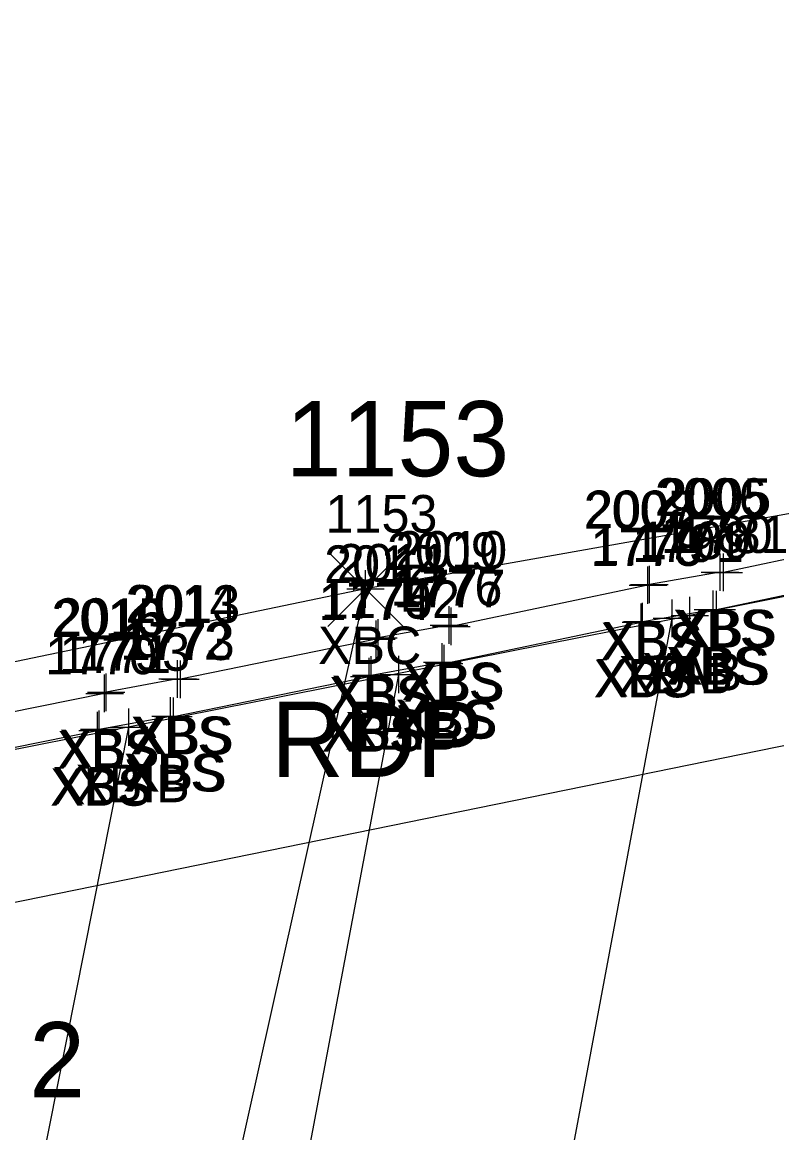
# Model space of a CAD drawing. Extents: x 1683147 to 1683637, y 416837 to 418211.
# Drawn here: x 1683260.07 to 1683280.15, y 417636.48 to 417666.03 of the extents above; entities that cross this region are included whole.
import ezdxf

# ---------------------------------------------------------------- set-up
doc = ezdxf.new("R2010")
doc.units = 0
for name, color, linetype in [('B_A', 7, 'Continuous'), ('B_I', 7, 'Continuous'), ('B_TIC', 7, 'Continuous'), ('BB', 7, 'Continuous'), ('BELB', 7, 'Continuous'), ('BSE', 7, 'Continuous'), ('BSUBM', 7, 'Continuous'), ('C_C', 7, 'Continuous'), ('LELB', 7, 'Continuous'), ('P_A', 7, 'Continuous'), ('P_I', 7, 'Continuous'), ('P_TIC', 7, 'Continuous'), ('PET', 7, 'Continuous')]:
    doc.layers.add(name, color=color, linetype=linetype)

msp = doc.modelspace()

# ---------------------------------------------------------------- linework, layer by layer
at = {"layer": 'B_TIC'}
for p, q in [((1683278.641, 417651.395), (1683278.717, 417651.395)), ((1683278.736, 417651.389), (1683278.812, 417651.389)), ((1683276.722, 417651.05), (1683276.798, 417651.05)), ((1683276.761, 417651.068), (1683276.837, 417651.068)), ((1683269.209, 417650.948), (1683269.285, 417650.948)), ((1683278.455, 417650.406), (1683278.53, 417650.406)), ((1683278.551, 417650.401), (1683278.627, 417650.401)), ((1683277.366, 417650.167), (1683277.441, 417650.167)), ((1683277.838, 417650.241), (1683277.914, 417650.241)), ((1683277.838, 417650.241), (1683277.914, 417650.241)), ((1683271.431, 417649.988), (1683271.507, 417649.988)), ((1683271.491, 417649.952), (1683271.567, 417649.952)), ((1683276.54, 417650.063), (1683276.616, 417650.063)), ((1683276.576, 417650.08), (1683276.651, 417650.08)), ((1683269.493, 417649.608), (1683269.569, 417649.608)), ((1683269.547, 417649.645), (1683269.623, 417649.645)), ((1683271.251, 417649.003), (1683271.326, 417649.003)), ((1683271.302, 417648.963), (1683271.377, 417648.963)), ((1683269.363, 417648.657), (1683269.438, 417648.657)), ((1683270.093, 417648.672), (1683270.169, 417648.672)), ((1683264.21, 417648.553), (1683264.286, 417648.553)), ((1683264.284, 417648.546), (1683264.36, 417648.546)), ((1683269.305, 417648.618), (1683269.381, 417648.618)), ((1683262.266, 417648.169), (1683262.342, 417648.169)), ((1683262.308, 417648.2), (1683262.384, 417648.2)), ((1683264.024, 417647.565), (1683264.1, 417647.565)), ((1683264.098, 417647.557), (1683264.174, 417647.557)), ((1683262.077, 417647.179), (1683262.153, 417647.179)), ((1683262.125, 417647.213), (1683262.2, 417647.213)), ((1683262.913, 417647.271), (1683262.989, 417647.271))]:
    msp.add_line(p, q, dxfattribs=at)
for points in [[(1683278.638, 417650.895), (1683278.638, 417651.895)], [(1683278.733, 417650.889), (1683278.733, 417651.889)], [(1683269.206, 417650.448), (1683269.206, 417651.448)], [(1683276.719, 417650.55), (1683276.719, 417651.55)], [(1683276.758, 417650.568), (1683276.758, 417651.568)], [(1683278.138, 417651.395), (1683279.138, 417651.395)], [(1683278.233, 417651.389), (1683279.233, 417651.389)], [(1683276.219, 417651.05), (1683277.219, 417651.05)], [(1683276.258, 417651.068), (1683277.258, 417651.068)], [(1683268.706, 417650.948), (1683269.706, 417650.948)], [(1683277.835, 417649.741), (1683277.835, 417650.741)], [(1683277.835, 417649.741), (1683277.835, 417650.741)], [(1683278.451, 417649.906), (1683278.451, 417650.906)], [(1683278.548, 417649.901), (1683278.548, 417650.901)], [(1683271.428, 417649.488), (1683271.428, 417650.488)], [(1683271.488, 417649.452), (1683271.488, 417650.452)], [(1683276.537, 417649.563), (1683276.537, 417650.563)], [(1683276.572, 417649.58), (1683276.572, 417650.58)], [(1683277.362, 417649.667), (1683277.362, 417650.667)], [(1683277.951, 417650.406), (1683278.951, 417650.406)], [(1683278.048, 417650.401), (1683279.048, 417650.401)], [(1683269.49, 417649.108), (1683269.49, 417650.108)], [(1683269.544, 417649.145), (1683269.544, 417650.145)], [(1683276.862, 417650.167), (1683277.862, 417650.167)], [(1683277.335, 417650.241), (1683278.335, 417650.241)], [(1683277.335, 417650.241), (1683278.335, 417650.241)], [(1683270.928, 417649.988), (1683271.928, 417649.988)], [(1683270.988, 417649.952), (1683271.988, 417649.952)], [(1683276.037, 417650.063), (1683277.037, 417650.063)], [(1683276.072, 417650.08), (1683277.072, 417650.08)], [(1683268.99, 417649.608), (1683269.99, 417649.608)], [(1683269.044, 417649.645), (1683270.044, 417649.645)], [(1683271.247, 417648.503), (1683271.247, 417649.503)], [(1683271.298, 417648.463), (1683271.298, 417649.463)], [(1683264.207, 417648.053), (1683264.207, 417649.053)], [(1683264.281, 417648.046), (1683264.281, 417649.046)], [(1683269.302, 417648.118), (1683269.302, 417649.118)], [(1683269.359, 417648.157), (1683269.359, 417649.157)], [(1683270.09, 417648.172), (1683270.09, 417649.172)], [(1683270.747, 417649.003), (1683271.747, 417649.003)], [(1683270.798, 417648.963), (1683271.798, 417648.963)], [(1683262.263, 417647.669), (1683262.263, 417648.669)], [(1683262.305, 417647.7), (1683262.305, 417648.7)], [(1683268.859, 417648.657), (1683269.859, 417648.657)], [(1683269.59, 417648.672), (1683270.59, 417648.672)], [(1683263.707, 417648.553), (1683264.707, 417648.553)], [(1683263.781, 417648.546), (1683264.781, 417648.546)], [(1683268.802, 417648.618), (1683269.802, 417648.618)], [(1683261.763, 417648.169), (1683262.763, 417648.169)], [(1683261.805, 417648.2), (1683262.805, 417648.2)], [(1683264.021, 417647.065), (1683264.021, 417648.065)], [(1683264.095, 417647.057), (1683264.095, 417648.057)], [(1683262.91, 417646.771), (1683262.91, 417647.771)], [(1683262.074, 417646.679), (1683262.074, 417647.679)], [(1683262.121, 417646.713), (1683262.121, 417647.713)], [(1683263.521, 417647.565), (1683264.521, 417647.565)], [(1683263.595, 417647.557), (1683264.595, 417647.557)], [(1683261.574, 417647.179), (1683262.574, 417647.179)], [(1683261.621, 417647.213), (1683262.621, 417647.213)], [(1683262.41, 417647.271), (1683263.41, 417647.271)]]:
    msp.add_lwpolyline(points, dxfattribs=at)
at = {"layer": 'BB'}
for points in [[(1683240.224, 417455.825), (1683249.612, 417504.3), (1683268.309, 417601.755), (1683277.362, 417650.167)], [(1683233.056, 417454.423), (1683242.375, 417502.873), (1683260.963, 417600.277), (1683270.09, 417648.672)], [(1683225.817, 417452.979), (1683235.185, 417501.44), (1683252.981, 417597.315), (1683262.91, 417647.271)]]:
    msp.add_lwpolyline(points, dxfattribs=at)
at = {"layer": 'BELB'}
msp.add_lwpolyline([(1683269.206, 417650.948), (1683260.393, 417611.397), (1683256.447, 417590.785), (1683246.822, 417543.339), (1683241.399, 417511.39), (1683234.932, 417474.067), (1683231.661, 417452.147)], dxfattribs=at)
at = {"layer": 'BSE'}
for points in [[(1683283.927, 417652.488), (1683278.733, 417651.389), (1683278.638, 417651.395), (1683276.758, 417651.068), (1683276.719, 417651.05), (1683271.488, 417649.952), (1683271.428, 417649.988), (1683269.544, 417649.645), (1683269.49, 417649.608), (1683264.281, 417648.546), (1683264.207, 417648.553), (1683262.305, 417648.2), (1683262.263, 417648.169), (1683257.032, 417647.113), (1683256.965, 417647.128), (1683255.09, 417646.775), (1683255.049, 417646.745), (1683249.804, 417645.71), (1683249.728, 417645.712), (1683247.888, 417645.363), (1683247.819, 417645.335), (1683242.553, 417644.24), (1683242.465, 417644.248), (1683239.325, 417643.593)], [(1683239.14, 417642.608), (1683242.28, 417643.262), (1683242.368, 417643.254), (1683247.633, 417644.348), (1683247.701, 417644.375), (1683249.539, 417644.722), (1683249.62, 417644.725), (1683254.86, 417645.755), (1683254.906, 417645.788), (1683256.78, 417646.141), (1683256.85, 417646.128), (1683262.074, 417647.179), (1683262.121, 417647.213), (1683264.021, 417647.565), (1683264.095, 417647.557), (1683269.302, 417648.618), (1683269.359, 417648.657), (1683271.247, 417649.003), (1683271.298, 417648.963), (1683276.537, 417650.063), (1683276.572, 417650.08), (1683278.451, 417650.406), (1683278.548, 417650.401), (1683283.741, 417651.499)]]:
    msp.add_lwpolyline(points, dxfattribs=at)
at = {"layer": 'BSUBM'}
for points in [[(1683291.811, 417666.031), (1683288.789, 417652.431), (1683277.835, 417650.241)], [(1683241.056, 417656.449), (1683237.912, 417642.88), (1683239.158, 417642.58), (1683277.835, 417650.241)]]:
    msp.add_lwpolyline(points, dxfattribs=at)
at = {"layer": 'LELB'}
msp.add_lwpolyline([(1683237.678, 417638.091), (1683288.082, 417648.362)], dxfattribs=at)
at = {"layer": 'P_TIC'}
for points in [[(1683268.206, 417649.948), (1683270.206, 417651.948)], [(1683270.206, 417649.948), (1683268.206, 417651.948)]]:
    msp.add_lwpolyline(points, dxfattribs=at)
at = {"layer": 'PET'}
msp.add_lwpolyline([(1683286.315, 417653.984), (1683269.206, 417650.948), (1683255.821, 417648.166), (1683241.392, 417644.923), (1683243.587, 417654.885)], dxfattribs=at)

# ---------------------------------------------------------------- texts
at = {"layer": 'B_A'}
for s, p in [('XBS', (1683277.378, 417649.395)), ('XBS', (1683277.473, 417649.389)), ('XBC', (1683267.942, 417648.948)), ('XBS', (1683275.459, 417649.05)), ('XBS', (1683275.498, 417649.068)), ('XAB', (1683276.555, 417648.241)), ('XAB', (1683276.555, 417648.241)), ('XBS', (1683277.192, 417648.406)), ('XBS', (1683277.288, 417648.401)), ('XBS', (1683270.168, 417647.988)), ('XBS', (1683270.228, 417647.952)), ('XBS', (1683275.277, 417648.063)), ('XBS', (1683275.312, 417648.08)), ('XBIB', (1683275.933, 417648.167)), ('XBS', (1683268.23, 417647.608)), ('XBS', (1683268.284, 417647.645)), ('XBS', (1683269.988, 417647.003)), ('XBS', (1683270.039, 417646.963)), ('XBS', (1683262.947, 417646.553)), ('XBS', (1683263.021, 417646.546)), ('XBS', (1683268.042, 417646.618)), ('XBS', (1683268.099, 417646.657)), ('XBIB', (1683268.661, 417646.672)), ('XBS', (1683261.003, 417646.169)), ('XBS', (1683261.045, 417646.2)), ('XBS', (1683262.761, 417645.565)), ('XBS', (1683262.835, 417645.557)), ('XBIB', (1683261.481, 417645.271)), ('XBS', (1683260.814, 417645.179)), ('XBS', (1683260.862, 417645.213))]:
    msp.add_text(s, height=1, dxfattribs=at).set_placement(p)
at = {"layer": 'B_I'}
for s, p in [('2006', (1683276.902, 417652.895)), ('2005', (1683277.024, 417652.889)), ('1153', (1683268.143, 417652.448)), ('2008', (1683275.01, 417652.55)), ('2007', (1683275.049, 417652.568)), ('1780', (1683277.062, 417651.906)), ('1781', (1683277.485, 417651.901)), ('2009', (1683269.775, 417651.452)), ('2010', (1683269.999, 417651.488)), ('1778', (1683275.191, 417651.563)), ('1779', (1683275.222, 417651.58)), ('1791', (1683276.299, 417651.667)), ('1789', (1683276.484, 417651.741)), ('1789', (1683276.484, 417651.741)), ('2012', (1683268.104, 417651.108)), ('2011', (1683268.442, 417651.145)), ('1776', (1683269.873, 417650.503)), ('1777', (1683269.952, 417650.463)), ('2014', (1683262.821, 417650.053)), ('2013', (1683262.895, 417650.046)), ('1774', (1683267.955, 417650.118)), ('1775', (1683268.013, 417650.157)), ('1792', (1683268.743, 417650.172)), ('2015', (1683260.919, 417649.7)), ('2016', (1683260.85, 417649.669)), ('1772', (1683262.674, 417649.065)), ('1773', (1683262.748, 417649.057)), ('1770', (1683260.684, 417648.679)), ('1771', (1683261.059, 417648.713)), ('1793', (1683261.563, 417648.771))]:
    msp.add_text(s, height=1, dxfattribs=at).set_placement(p)
at = {"layer": 'C_C'}
msp.add_text('HIGHWAY DAPARTMENT BM 191 2 2', height=2, dxfattribs=at).set_placement((1683215.377, 417637.421))
at = {"layer": 'P_A'}
msp.add_text('RDP', height=2, dxfattribs=at).set_placement((1683266.694, 417645.948))
at = {"layer": 'P_I'}
msp.add_text('1153', height=2, dxfattribs=at).set_placement((1683267.08, 417653.948))

doc.saveas('drawing.dxf')
